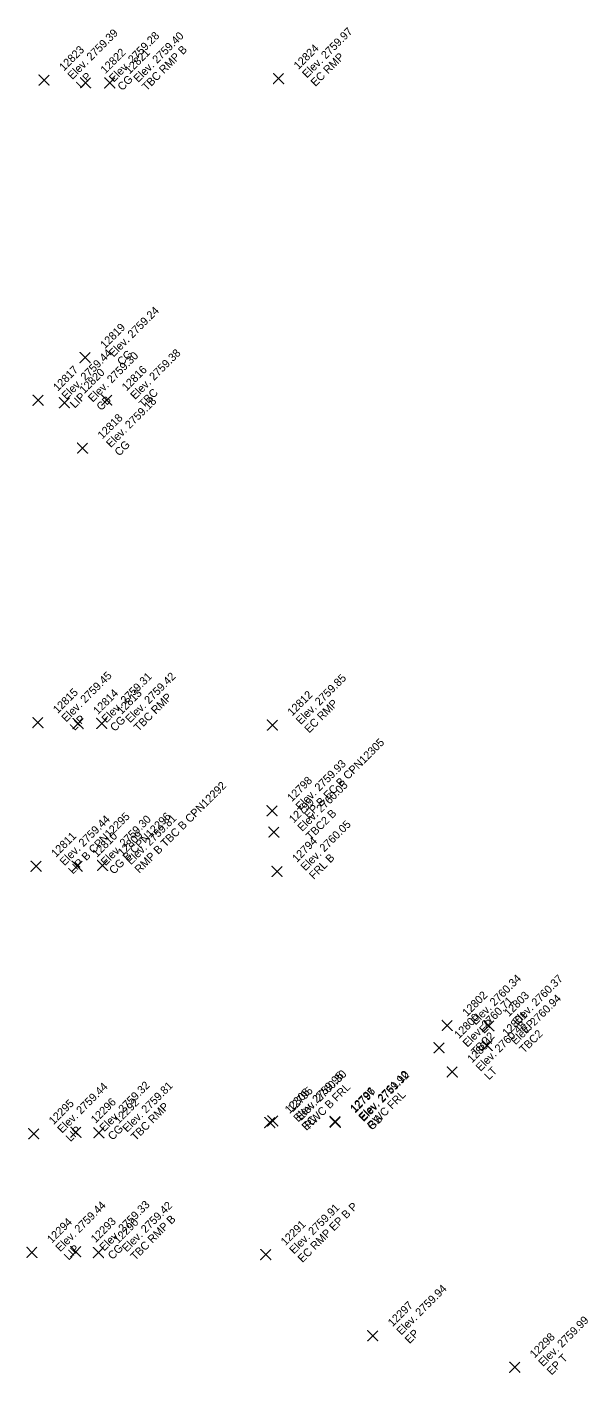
# Model space of a CAD drawing. Extents: x 2493999 to 2503109, y 700767 to 706646.
# Drawn here: x 2502312.27 to 2502329.1, y 702337.08 to 702377.51 of the extents above; entities that cross this region are included whole.
import ezdxf

# ---------------------------------------------------------------- set-up
doc = ezdxf.new("R2010")
doc.units = 0
doc.layers.add('ALG_CL_BLUE_Horiz', color=7, linetype='Continuous')
doc.layers.add('DES_SURFACE_Existing-Ground', color=7, linetype='Continuous')

msp = doc.modelspace()

# ---------------------------------------------------------------- linework, layer by layer
at = {"layer": 'ALG_CL_BLUE_Horiz'}
for points in [[(2502312.785, 702375.918), (2502312.635, 702376.068), (2502312.785, 702375.918), (2502312.635, 702375.768), (2502312.785, 702375.918), (2502312.935, 702375.768), (2502312.785, 702375.918), (2502312.935, 702376.068)], [(2502314.029, 702375.837), (2502313.879, 702375.987), (2502314.029, 702375.837), (2502313.879, 702375.687), (2502314.029, 702375.837), (2502314.179, 702375.687), (2502314.029, 702375.837), (2502314.179, 702375.987)], [(2502314.758, 702375.831), (2502314.608, 702375.981), (2502314.758, 702375.831), (2502314.608, 702375.681), (2502314.758, 702375.831), (2502314.908, 702375.681), (2502314.758, 702375.831), (2502314.908, 702375.981)], [(2502319.82, 702375.964), (2502319.67, 702376.114), (2502319.82, 702375.964), (2502319.67, 702375.814), (2502319.82, 702375.964), (2502319.97, 702375.814), (2502319.82, 702375.964), (2502319.97, 702376.114)], [(2502314.017, 702367.593), (2502313.867, 702367.743), (2502314.017, 702367.593), (2502313.867, 702367.443), (2502314.017, 702367.593), (2502314.167, 702367.443), (2502314.017, 702367.593), (2502314.167, 702367.743)], [(2502312.605, 702366.316), (2502312.455, 702366.466), (2502312.605, 702366.316), (2502312.455, 702366.166), (2502312.605, 702366.316), (2502312.755, 702366.166), (2502312.605, 702366.316), (2502312.755, 702366.466)], [(2502314.666, 702366.322), (2502314.516, 702366.472), (2502314.666, 702366.322), (2502314.516, 702366.172), (2502314.666, 702366.322), (2502314.816, 702366.172), (2502314.666, 702366.322), (2502314.816, 702366.472)], [(2502313.398, 702366.241), (2502313.248, 702366.391), (2502313.398, 702366.241), (2502313.248, 702366.091), (2502313.398, 702366.241), (2502313.548, 702366.091), (2502313.398, 702366.241), (2502313.548, 702366.391)], [(2502313.94, 702364.879), (2502313.79, 702365.029), (2502313.94, 702364.879), (2502313.79, 702364.729), (2502313.94, 702364.879), (2502314.09, 702364.729), (2502313.94, 702364.879), (2502314.09, 702365.029)], [(2502312.601, 702356.646), (2502312.451, 702356.796), (2502312.601, 702356.646), (2502312.451, 702356.496), (2502312.601, 702356.646), (2502312.751, 702356.496), (2502312.601, 702356.646), (2502312.751, 702356.796)], [(2502313.806, 702356.619), (2502313.656, 702356.769), (2502313.806, 702356.619), (2502313.656, 702356.469), (2502313.806, 702356.619), (2502313.956, 702356.469), (2502313.806, 702356.619), (2502313.956, 702356.769)], [(2502314.516, 702356.623), (2502314.366, 702356.773), (2502314.516, 702356.623), (2502314.366, 702356.473), (2502314.516, 702356.623), (2502314.666, 702356.473), (2502314.516, 702356.623), (2502314.666, 702356.773)], [(2502319.632, 702356.574), (2502319.482, 702356.724), (2502319.632, 702356.574), (2502319.482, 702356.424), (2502319.632, 702356.574), (2502319.782, 702356.424), (2502319.632, 702356.574), (2502319.782, 702356.724)], [(2502319.624, 702354.003), (2502319.474, 702354.153), (2502319.624, 702354.003), (2502319.474, 702353.853), (2502319.624, 702354.003), (2502319.774, 702353.853), (2502319.624, 702354.003), (2502319.774, 702354.153)], [(2502319.679, 702353.364), (2502319.529, 702353.514), (2502319.679, 702353.364), (2502319.529, 702353.214), (2502319.679, 702353.364), (2502319.829, 702353.214), (2502319.679, 702353.364), (2502319.829, 702353.514)], [(2502312.547, 702352.339), (2502312.397, 702352.489), (2502312.547, 702352.339), (2502312.397, 702352.189), (2502312.547, 702352.339), (2502312.697, 702352.189), (2502312.547, 702352.339), (2502312.697, 702352.489)], [(2502313.778, 702352.338), (2502313.628, 702352.488), (2502313.778, 702352.338), (2502313.628, 702352.188), (2502313.778, 702352.338), (2502313.928, 702352.188), (2502313.778, 702352.338), (2502313.928, 702352.488)], [(2502314.543, 702352.367), (2502314.393, 702352.517), (2502314.543, 702352.367), (2502314.393, 702352.217), (2502314.543, 702352.367), (2502314.693, 702352.217), (2502314.543, 702352.367), (2502314.693, 702352.517)], [(2502319.772, 702352.186), (2502319.622, 702352.336), (2502319.772, 702352.186), (2502319.622, 702352.036), (2502319.772, 702352.186), (2502319.922, 702352.036), (2502319.772, 702352.186), (2502319.922, 702352.336)], [(2502324.877, 702347.564), (2502324.727, 702347.714), (2502324.877, 702347.564), (2502324.727, 702347.414), (2502324.877, 702347.564), (2502325.027, 702347.414), (2502324.877, 702347.564), (2502325.027, 702347.714)], [(2502326.129, 702347.556), (2502325.979, 702347.706), (2502326.129, 702347.556), (2502325.979, 702347.406), (2502326.129, 702347.556), (2502326.279, 702347.406), (2502326.129, 702347.556), (2502326.279, 702347.706)], [(2502326.077, 702346.966), (2502325.927, 702347.116), (2502326.077, 702346.966), (2502325.927, 702346.816), (2502326.077, 702346.966), (2502326.227, 702346.816), (2502326.077, 702346.966), (2502326.227, 702347.116)], [(2502324.633, 702346.898), (2502324.483, 702347.048), (2502324.633, 702346.898), (2502324.483, 702346.748), (2502324.633, 702346.898), (2502324.783, 702346.748), (2502324.633, 702346.898), (2502324.783, 702347.048)], [(2502325.025, 702346.172), (2502324.875, 702346.322), (2502325.025, 702346.172), (2502324.875, 702346.022), (2502325.025, 702346.172), (2502325.175, 702346.022), (2502325.025, 702346.172), (2502325.175, 702346.322)], [(2502319.554, 702344.651), (2502319.404, 702344.801), (2502319.554, 702344.651), (2502319.404, 702344.501), (2502319.554, 702344.651), (2502319.704, 702344.501), (2502319.554, 702344.651), (2502319.704, 702344.801)], [(2502319.643, 702344.7), (2502319.493, 702344.85), (2502319.643, 702344.7), (2502319.493, 702344.55), (2502319.643, 702344.7), (2502319.793, 702344.55), (2502319.643, 702344.7), (2502319.793, 702344.85)], [(2502321.512, 702344.688), (2502321.362, 702344.838), (2502321.512, 702344.688), (2502321.362, 702344.538), (2502321.512, 702344.688), (2502321.662, 702344.538), (2502321.512, 702344.688), (2502321.662, 702344.838)], [(2502321.521, 702344.662), (2502321.371, 702344.812), (2502321.521, 702344.662), (2502321.371, 702344.512), (2502321.521, 702344.662), (2502321.671, 702344.512), (2502321.521, 702344.662), (2502321.671, 702344.812)], [(2502312.477, 702344.319), (2502312.327, 702344.469), (2502312.477, 702344.319), (2502312.327, 702344.169), (2502312.477, 702344.319), (2502312.627, 702344.169), (2502312.477, 702344.319), (2502312.627, 702344.469)], [(2502313.739, 702344.36), (2502313.589, 702344.51), (2502313.739, 702344.36), (2502313.589, 702344.21), (2502313.739, 702344.36), (2502313.889, 702344.21), (2502313.739, 702344.36), (2502313.889, 702344.51)], [(2502314.43, 702344.346), (2502314.28, 702344.496), (2502314.43, 702344.346), (2502314.28, 702344.196), (2502314.43, 702344.346), (2502314.58, 702344.196), (2502314.43, 702344.346), (2502314.58, 702344.496)], [(2502312.423, 702340.761), (2502312.273, 702340.911), (2502312.423, 702340.761), (2502312.273, 702340.611), (2502312.423, 702340.761), (2502312.573, 702340.611), (2502312.423, 702340.761), (2502312.573, 702340.911)], [(2502313.738, 702340.781), (2502313.588, 702340.931), (2502313.738, 702340.781), (2502313.588, 702340.631), (2502313.738, 702340.781), (2502313.888, 702340.631), (2502313.738, 702340.781), (2502313.888, 702340.931)], [(2502314.415, 702340.754), (2502314.265, 702340.904), (2502314.415, 702340.754), (2502314.265, 702340.604), (2502314.415, 702340.754), (2502314.565, 702340.604), (2502314.415, 702340.754), (2502314.565, 702340.904)], [(2502319.433, 702340.692), (2502319.283, 702340.842), (2502319.433, 702340.692), (2502319.283, 702340.542), (2502319.433, 702340.692), (2502319.583, 702340.542), (2502319.433, 702340.692), (2502319.583, 702340.842)], [(2502322.645, 702338.261), (2502322.495, 702338.411), (2502322.645, 702338.261), (2502322.495, 702338.111), (2502322.645, 702338.261), (2502322.795, 702338.111), (2502322.645, 702338.261), (2502322.795, 702338.411)], [(2502326.901, 702337.317), (2502326.751, 702337.467), (2502326.901, 702337.317), (2502326.751, 702337.167), (2502326.901, 702337.317), (2502327.051, 702337.167), (2502326.901, 702337.317), (2502327.051, 702337.467)]]:
    msp.add_lwpolyline(points, dxfattribs=at)

# ---------------------------------------------------------------- texts
at = {"layer": 'DES_SURFACE_Existing-Ground'}
for s, p in [('Elev. 2759.39', (2502313.634, 702375.918)), ('Elev. 2759.97', (2502320.669, 702375.964)), ('Elev. 2759.28', (2502314.878, 702375.837)), ('Elev. 2759.40', (2502315.607, 702375.831)), ('12824', (2502320.414, 702376.219)), ('12823', (2502313.379, 702376.173)), ('12822', (2502314.623, 702376.092)), ('12821', (2502315.352, 702376.086)), ('TBC RMP B', (2502315.861, 702375.576)), ('EC RMP', (2502320.923, 702375.709)), ('LIP', (2502313.888, 702375.663)), ('CG', (2502315.132, 702375.582)), ('Elev. 2759.24', (2502314.866, 702367.593)), ('12819', (2502314.611, 702367.848)), ('Elev. 2759.44', (2502313.454, 702366.316)), ('Elev. 2759.30', (2502314.247, 702366.241)), ('CG', (2502315.12, 702367.338)), ('Elev. 2759.38', (2502315.515, 702366.322)), ('12817', (2502313.199, 702366.571)), ('12816', (2502315.26, 702366.577)), ('12820', (2502313.992, 702366.496)), ('LIP', (2502313.708, 702366.061)), ('TBC', (2502315.769, 702366.067)), ('CB', (2502314.501, 702365.986)), ('Elev. 2759.18', (2502314.789, 702364.879)), ('12818', (2502314.534, 702365.134)), ('CG', (2502315.043, 702364.624)), ('Elev. 2759.45', (2502313.45, 702356.646)), ('Elev. 2759.31', (2502314.655, 702356.619)), ('Elev. 2759.42', (2502315.365, 702356.623)), ('Elev. 2759.85', (2502320.481, 702356.574)), ('12815', (2502313.195, 702356.901)), ('12814', (2502314.4, 702356.874)), ('12813', (2502315.11, 702356.878)), ('12812', (2502320.226, 702356.829)), ('TBC RMP', (2502315.619, 702356.368)), ('EC RMP', (2502320.735, 702356.319)), ('LIP', (2502313.704, 702356.391)), ('CG', (2502314.909, 702356.364)), ('EP B EC B CPN12305', (2502320.727, 702353.748)), ('Elev. 2759.93', (2502320.473, 702354.003)), ('RMP B TBC B CPN12292', (2502315.646, 702352.112)), ('12798', (2502320.218, 702354.258)), ('Elev. 2760.05', (2502320.528, 702353.364)), ('12799', (2502320.273, 702353.619)), ('LIP B CPN12295', (2502313.65, 702352.084)), ('CG B CPN12296', (2502314.881, 702352.083)), ('TBC2 B', (2502320.782, 702353.109)), ('Elev. 2759.44', (2502313.396, 702352.339)), ('Elev. 2759.30', (2502314.627, 702352.338)), ('Elev. 2759.81', (2502315.392, 702352.367)), ('Elev. 2760.05', (2502320.621, 702352.186)), ('12811', (2502313.141, 702352.594)), ('12810', (2502314.372, 702352.593)), ('12809', (2502315.137, 702352.622)), ('12794', (2502320.366, 702352.441)), ('FRL B', (2502320.875, 702351.931)), ('Elev. 2760.34', (2502325.726, 702347.564)), ('Elev. 2760.37', (2502326.978, 702347.556)), ('Elev. 2760.71', (2502325.482, 702346.898)), ('12802', (2502325.471, 702347.819)), ('12803', (2502326.723, 702347.811)), ('Elev. 2760.94', (2502326.926, 702346.966)), ('12800', (2502325.227, 702347.153)), ('12801', (2502326.671, 702347.221)), ('Elev. 2760.48', (2502325.874, 702346.172)), ('EP', (2502325.98, 702347.309)), ('EP', (2502327.232, 702347.301)), ('12804', (2502325.619, 702346.427)), ('TBC2', (2502325.736, 702346.643)), ('TBC2', (2502327.18, 702346.711)), ('LT', (2502326.128, 702345.917)), ('Elev. 2759.44', (2502313.326, 702344.319)), ('Elev. 2759.32', (2502314.588, 702344.36)), ('Elev. 2759.81', (2502315.279, 702344.346)), ('Elev. 2759.95', (2502320.403, 702344.651)), ('Elev. 2760.30', (2502320.492, 702344.7)), ('Elev. 2761.10', (2502322.361, 702344.688)), ('Elev. 2759.92', (2502322.37, 702344.662)), ('12305', (2502320.148, 702344.906)), ('12795', (2502320.237, 702344.955)), ('RWC B FRL', (2502320.746, 702344.445)), ('12796', (2502322.106, 702344.943)), ('12797', (2502322.115, 702344.917)), ('RWC FRL', (2502322.615, 702344.433)), ('12295', (2502313.071, 702344.574)), ('12296', (2502314.333, 702344.615)), ('12292', (2502315.024, 702344.601)), ('TBC RMP', (2502315.533, 702344.091)), ('EC', (2502320.657, 702344.396)), ('GS', (2502322.624, 702344.407)), ('LIP', (2502313.58, 702344.064)), ('CG', (2502314.842, 702344.105)), ('Elev. 2759.44', (2502313.272, 702340.761)), ('Elev. 2759.33', (2502314.587, 702340.781)), ('Elev. 2759.42', (2502315.264, 702340.754)), ('EC RMP EP B P', (2502320.536, 702340.437)), ('TBC RMP B', (2502315.518, 702340.499)), ('Elev. 2759.91', (2502320.282, 702340.692)), ('12294', (2502313.017, 702341.016)), ('12293', (2502314.332, 702341.036)), ('12290', (2502315.009, 702341.009)), ('12291', (2502320.027, 702340.947)), ('LIP', (2502313.526, 702340.506)), ('CG', (2502314.841, 702340.526)), ('Elev. 2759.94', (2502323.494, 702338.261)), ('12297', (2502323.239, 702338.516)), ('Elev. 2759.99', (2502327.75, 702337.317)), ('EP', (2502323.748, 702338.006)), ('12298', (2502327.495, 702337.572)), ('EP T', (2502328.004, 702337.062))]:
    msp.add_text(s, height=0.24, rotation=45, dxfattribs=at).set_placement(p)

doc.saveas('drawing.dxf')
